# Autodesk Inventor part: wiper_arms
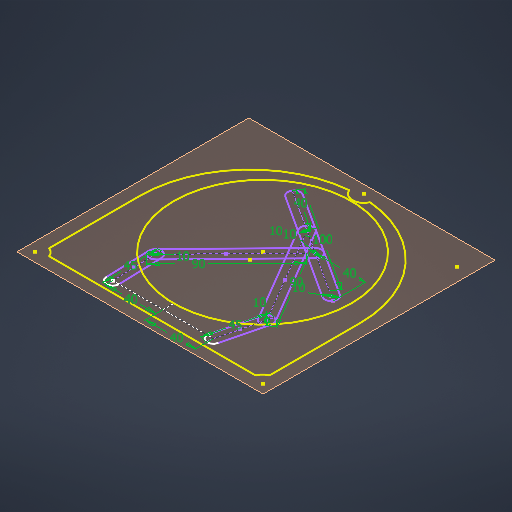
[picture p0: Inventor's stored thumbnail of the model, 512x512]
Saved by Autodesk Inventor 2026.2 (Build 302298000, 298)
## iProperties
Created: 2026-03
Part Number: wiper_arms
Material: Generic
Document SubType Name: Modeling
Designer: Tathagata Sikdar
Density: 1 g/cm^3
Appearance: Default
Author: Tathagata Sikdar
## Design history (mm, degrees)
workplane "Work Plane1"
sketch "Sketch1"
  geometry: L1 (-87.574, 76.889)-(-87.574, 4.83) reference; L2 (87.574, 4.83)-(87.574, 76.889) reference; L3 (82.089, 82.375)-(-82.089, 82.375) reference; L4 (0, 82.375)-(0, 65.328); L5 (39.825, 78.848)-(41.4, 33.876); L6 (35.003, 73.676)-(36.228, 38.698); L7 (46.222, 39.048)-(44.997, 74.026); L8 (-38.793, 78.704)-(-49.654, 35.034); L9 (-44.852, 75.058)-(-53.299, 41.093); L10 (-43.595, 38.679)-(-35.148, 72.645); L11 (44.716, 42.453)-(-18.114, -21.987); L12 (37.645, 42.363)-(-25.184, -22.076); L13 (-18.024, -29.057)-(44.805, 35.382); L14 (-50.98, 44.197)-(-5.39, -33.402); L15 (-52.758, 37.353)-(-7.169, -40.246); L16 (1.454, -35.18)-(-44.136, 42.419); L17 (30.712, -59.463)-(-53.212, -5.087); L18 (29.235, -52.548)-(-54.689, 1.828); L19 (-60.127, -6.565)-(23.797, -60.941); L20 (26.516, -56.745)-(-11.25, -32.275); L21 (-53.212, -5.087)-(-21.604, -25.567); L22 (30.712, -59.463)-(-2.858, -37.713); L23 (0, 73.851)-(-40, 73.851); L24 (0, 73.851)-(40, 73.851); A1 r 87.574 centre (0, 4.83) between (-87.574, 4.83) and (-8.334, -82.347) reference; A2 r 9 centre (0, -85.744) between (8.334, -82.347) and (-8.334, -82.347) reference; A3 r 87.574 centre (0, 4.83) between (8.334, -82.347) and (87.574, 4.83) reference; A4 r 9 centre (90.574, 85.375) between (82.089, 82.375) and (87.574, 76.889) reference; A5 r 9 centre (-90.574, 85.375) between (-87.574, 76.889) and (-82.089, 82.375) reference; A6 r 5 centre (40, 73.851) between (44.997, 74.026) and (35.003, 73.676); A7 r 5 centre (41.225, 38.873) between (36.228, 38.698) and (46.222, 39.048); A8 r 5 centre (-40, 73.851) between (-35.148, 72.645) and (-44.852, 75.058); A9 r 5 centre (-48.447, 39.886) between (-53.299, 41.093) and (-43.595, 38.679); A10 r 5 centre (41.225, 38.873) between (44.805, 35.382) and (37.645, 42.363); A11 r 5 centre (-21.604, -25.567) between (-25.184, -22.076) and (-18.024, -29.057); A12 r 5 centre (-48.447, 39.886) between (-44.136, 42.419) and (-52.758, 37.353); A13 r 5 centre (-2.858, -37.713) between (-7.169, -40.246) and (1.454, -35.18); A14 r 5 centre (26.516, -56.745) between (23.797, -60.941) and (29.235, -52.548); A15 r 5 centre (-57.408, -2.369) between (-54.689, 1.828) and (-60.127, -6.565); 7 further points
  constraints: 52 end point, 31 point on circle, 20 tangent, 12 point on line, 10 centre point, 7 midpoint, 5 coincident, 5 parallel, 2 horizontal, 1 collinear, 1 vertical, 1 vertical alignment, 1 other
  dimensions: "d4" = 45 distance of L5.start L5.end; "d5" = 10 diameter of A7; "d6" = 45 distance of L8.start L8.end; "d7" = 10 diameter of A9; "d8" = 90 distance of L11.start L11.end; "d9" = 10 diameter of A11; "d10" = 90 distance of L14.start L14.end; "d11" = 10 diameter of A13; "d12" = 100 distance of L17.start L17.end; "d13" = 10 diameter of A15; "d15" = 40 distance of L17.start L22.end; "d16" = 40 distance of L23.start L23.end; "d17" = 40 distance of L23.start L24.end; "d18" = 40 horizontal distance of point (-61.604, 0.35) A11.centre
  node "Reference1"
